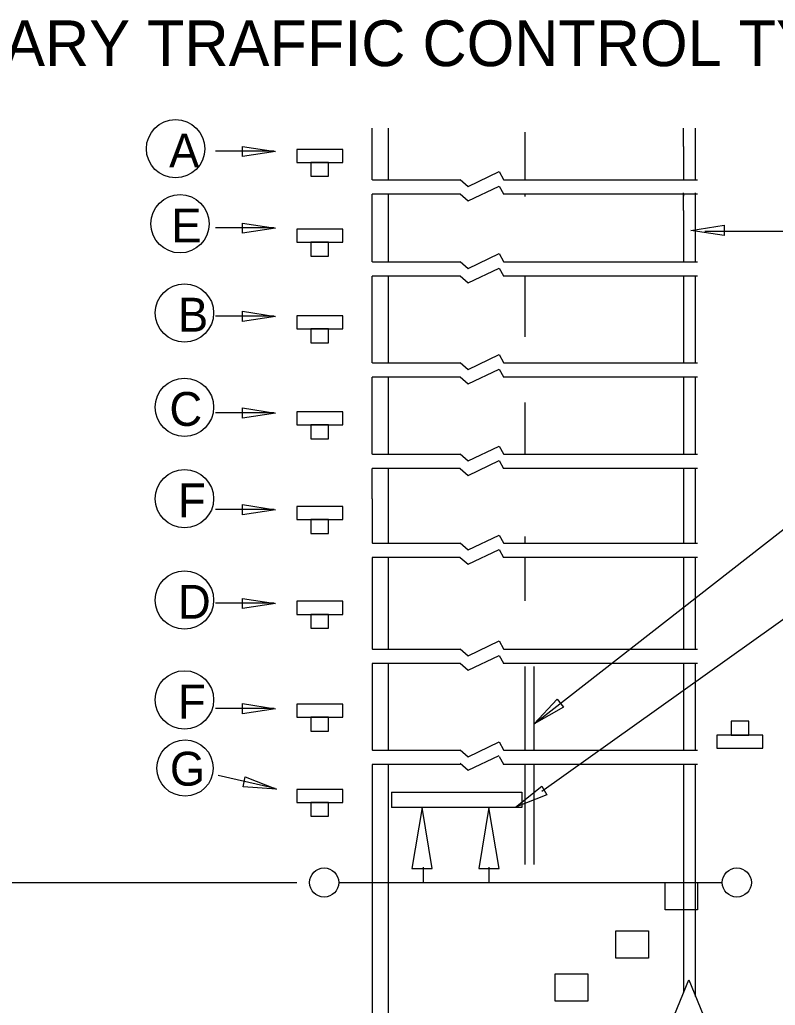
# Model space of a CAD drawing. Extents: x 1531.2 to 1538.6, y 1529.6 to 1539.7.
# Drawn here: x 1533.576 to 1535.359, y 1537.377 to 1539.704 of the extents above; entities that cross this region are included whole.
import ezdxf

# ---------------------------------------------------------------- set-up
doc = ezdxf.new("R2010")
doc.units = 0
for name, color, linetype in [('DETL-DIMS', 7, 'Continuous'), ('DETL-LINE', 7, 'Continuous'), ('DETL-NOTE', 7, 'Continuous'), ('DETL-TITL', 7, 'Continuous')]:
    doc.layers.add(name, color=color, linetype=linetype)

msp = doc.modelspace()

# ---------------------------------------------------------------- linework, layer by layer
at = {"layer": 'DETL-DIMS'}
for p, q in [((1534.1757, 1539.3929), (1534.0377, 1539.3929)), ((1534.6337, 1539.31), (1534.7074, 1539.3451)), ((1534.7074, 1539.3451), (1534.7174, 1539.3263)), ((1534.4085, 1539.3259), (1534.6147, 1539.3259)), ((1534.6147, 1539.3263), (1534.6337, 1539.31)), ((1534.7173, 1539.3259), (1535.1751, 1539.3259)), ((1534.6337, 1539.276), (1534.7074, 1539.311)), ((1534.7074, 1539.311), (1534.7174, 1539.2923)), ((1534.6149, 1539.2919), (1534.4085, 1539.2919)), ((1534.6147, 1539.2923), (1534.6337, 1539.276)), ((1535.1751, 1539.2919), (1534.7167, 1539.2919)), ((1534.1757, 1539.212), (1534.0377, 1539.212)), ((1535.1925, 1539.2044), (1535.7088, 1539.2044)), ((1534.4085, 1539.1323), (1534.6147, 1539.1323)), ((1534.6147, 1539.1327), (1534.6337, 1539.1164)), ((1534.6337, 1539.1164), (1534.7074, 1539.1515)), ((1534.7074, 1539.1515), (1534.7174, 1539.1327)), ((1534.7173, 1539.1323), (1535.1751, 1539.1323)), ((1534.6337, 1539.0824), (1534.7074, 1539.1174)), ((1534.7074, 1539.1174), (1534.7174, 1539.0987)), ((1534.6149, 1539.0983), (1534.4085, 1539.0983)), ((1534.6147, 1539.0987), (1534.6337, 1539.0824)), ((1535.1751, 1539.0983), (1534.7167, 1539.0983)), ((1534.1757, 1539.0038), (1534.0377, 1539.0038)), ((1534.6337, 1538.878), (1534.7074, 1538.9131)), ((1534.7074, 1538.9131), (1534.7174, 1538.8944)), ((1534.4085, 1538.8939), (1534.6147, 1538.8939)), ((1534.6147, 1538.8944), (1534.6337, 1538.878)), ((1534.6337, 1538.844), (1534.7074, 1538.879)), ((1534.7074, 1538.879), (1534.7174, 1538.8603)), ((1534.7173, 1538.8939), (1535.1751, 1538.8939)), ((1534.6149, 1538.8599), (1534.4085, 1538.8599)), ((1534.6147, 1538.8603), (1534.6337, 1538.844)), ((1535.1751, 1538.8599), (1534.7167, 1538.8599)), ((1534.1757, 1538.7755), (1534.0377, 1538.7755)), ((1534.7897, 1538.0412), (1535.7183, 1538.7668)), ((1534.6337, 1538.662), (1534.7074, 1538.6971)), ((1534.7074, 1538.6971), (1534.7174, 1538.6784)), ((1534.4085, 1538.6779), (1534.6147, 1538.6779)), ((1534.6147, 1538.6784), (1534.6337, 1538.662)), ((1534.7173, 1538.6779), (1535.1751, 1538.6779)), ((1534.6149, 1538.6439), (1534.4085, 1538.6439)), ((1534.6147, 1538.6443), (1534.6337, 1538.628)), ((1534.6337, 1538.628), (1534.7074, 1538.663)), ((1534.7074, 1538.663), (1534.7174, 1538.6443)), ((1535.1751, 1538.6439), (1534.7167, 1538.6439)), ((1534.1757, 1538.5473), (1534.0377, 1538.5473)), ((1534.8078, 1537.8823), (1535.7074, 1538.5239)), ((1534.6337, 1538.4521), (1534.7074, 1538.4871)), ((1534.7074, 1538.4871), (1534.7174, 1538.4684)), ((1534.4085, 1538.4679), (1534.6147, 1538.4679)), ((1534.6147, 1538.4684), (1534.6337, 1538.4521)), ((1534.7173, 1538.4679), (1535.1751, 1538.4679)), ((1534.6149, 1538.4339), (1534.4085, 1538.4339)), ((1534.6147, 1538.4344), (1534.6337, 1538.4181)), ((1534.6337, 1538.4181), (1534.7074, 1538.4531)), ((1534.7074, 1538.4531), (1534.7174, 1538.4344)), ((1535.1751, 1538.4339), (1534.7167, 1538.4339)), ((1534.1757, 1538.3259), (1534.0377, 1538.3259)), ((1534.6337, 1538.2021), (1534.7074, 1538.2371)), ((1534.7074, 1538.2371), (1534.7174, 1538.2184)), ((1534.4085, 1538.2179), (1534.6147, 1538.2179)), ((1534.6147, 1538.2184), (1534.6337, 1538.2021)), ((1534.6337, 1538.168), (1534.7074, 1538.203)), ((1534.7074, 1538.203), (1534.7174, 1538.1843)), ((1534.7173, 1538.2179), (1535.1751, 1538.2179)), ((1534.6149, 1538.1839), (1534.4085, 1538.1839)), ((1534.6147, 1538.1843), (1534.6337, 1538.168)), ((1535.1751, 1538.1839), (1534.7167, 1538.1839)), ((1534.1757, 1538.0777), (1534.0377, 1538.0777)), ((1534.6337, 1537.9637), (1534.7074, 1537.9987)), ((1534.7074, 1537.9987), (1534.7174, 1537.98)), ((1534.4085, 1537.9795), (1534.6147, 1537.9795)), ((1534.6147, 1537.98), (1534.6337, 1537.9637)), ((1534.6337, 1537.932), (1534.7074, 1537.967)), ((1534.7173, 1537.9795), (1535.1751, 1537.9795)), ((1534.6149, 1537.9455), (1534.4072, 1537.9455)), ((1534.6147, 1537.9483), (1534.6337, 1537.932)), ((1534.7074, 1537.9646), (1534.7174, 1537.9459)), ((1535.1751, 1537.9455), (1534.7167, 1537.9455)), ((1534.1783, 1537.8885), (1534.0436, 1537.9191)), ((1533.4083, 1537.6671), (1534.2295, 1537.6671))]:
    msp.add_line(p, q, dxfattribs=at)
for points in [[(1534.1795, 1539.3924), (1534.101, 1539.3804), (1534.101, 1539.4044)], [(1534.1795, 1539.2115), (1534.101, 1539.1995), (1534.101, 1539.2235)], [(1535.1597, 1539.2063), (1535.2383, 1539.2183), (1535.2383, 1539.1943)], [(1534.1795, 1539.0033), (1534.101, 1538.9913), (1534.101, 1539.0153)], [(1534.1795, 1538.7751), (1534.101, 1538.7631), (1534.101, 1538.7871)], [(1534.1795, 1538.5468), (1534.101, 1538.5348), (1534.101, 1538.5588)], [(1534.1795, 1538.3255), (1534.101, 1538.3135), (1534.101, 1538.3375)], [(1534.1795, 1538.0772), (1534.101, 1538.0652), (1534.101, 1538.0892)], [(1534.7897, 1538.0412), (1534.8438, 1538.0994), (1534.8587, 1538.0806)], [(1534.1818, 1537.8872), (1534.1026, 1537.8929), (1534.1079, 1537.9163)], [(1534.7455, 1537.8449), (1534.8077, 1537.8943), (1534.8197, 1537.8735)]]:
    msp.add_lwpolyline(points, close=True, dxfattribs=at)
at = {"layer": 'DETL-LINE'}
for p, q in [((1534.4072, 1539.3996), (1534.4072, 1539.4477)), ((1534.4456, 1539.4043), (1534.4456, 1539.4477)), ((1534.7687, 1539.3259), (1534.7687, 1539.4383)), ((1535.1419, 1539.4043), (1535.1419, 1539.4477)), ((1535.1706, 1539.3777), (1535.1706, 1539.4477)), ((1534.4072, 1539.3255), (1534.4072, 1539.3996)), ((1534.4456, 1539.3259), (1534.4456, 1539.4043)), ((1535.1419, 1539.4043), (1535.1419, 1539.3259)), ((1535.1706, 1539.3259), (1535.1706, 1539.3777)), ((1534.4085, 1539.3259), (1534.4072, 1539.3259)), ((1535.1419, 1539.2531), (1535.1419, 1539.2946)), ((1535.1706, 1539.2531), (1535.1706, 1539.2946)), ((1534.4085, 1539.2919), (1534.4072, 1539.2919)), ((1534.4072, 1539.2872), (1534.4072, 1539.2919)), ((1534.4072, 1539.2531), (1534.4072, 1539.2907)), ((1534.4456, 1539.2872), (1534.4456, 1539.2919)), ((1534.4456, 1539.2531), (1534.4456, 1539.2891)), ((1534.7687, 1539.2863), (1534.7687, 1539.2919)), ((1535.1419, 1539.2919), (1535.1419, 1539.2872)), ((1535.1706, 1539.2872), (1535.1706, 1539.2919)), ((1534.4072, 1539.1323), (1534.4072, 1539.2531)), ((1534.4456, 1539.1323), (1534.4456, 1539.2531)), ((1535.1419, 1539.2531), (1535.1419, 1539.1323)), ((1535.1706, 1539.1323), (1535.1706, 1539.2531)), ((1534.4085, 1539.1323), (1534.4072, 1539.1323)), ((1534.4085, 1539.0983), (1534.4072, 1539.0983)), ((1534.4072, 1538.8939), (1534.4072, 1539.0983)), ((1534.4456, 1538.8939), (1534.4456, 1539.0983)), ((1534.7687, 1538.9546), (1534.7687, 1539.0983)), ((1535.1419, 1539.0983), (1535.1419, 1538.8939)), ((1535.1706, 1538.8939), (1535.1706, 1539.0983)), ((1534.4085, 1538.8939), (1534.4072, 1538.8939)), ((1534.4085, 1538.8599), (1534.4072, 1538.8599)), ((1534.4072, 1538.6779), (1534.4072, 1538.8599)), ((1534.4456, 1538.6779), (1534.4456, 1538.8599)), ((1535.1419, 1538.8599), (1535.1419, 1538.6779)), ((1535.1706, 1538.6779), (1535.1706, 1538.8599)), ((1534.7687, 1538.6779), (1534.7687, 1538.7999)), ((1534.4085, 1538.6779), (1534.4072, 1538.6779)), ((1534.4072, 1538.5725), (1534.4072, 1538.6439)), ((1534.4085, 1538.6439), (1534.4072, 1538.6439)), ((1534.4456, 1538.4679), (1534.4456, 1538.6439)), ((1535.1419, 1538.6439), (1535.1419, 1538.4679)), ((1535.1706, 1538.5725), (1535.1706, 1538.6439)), ((1534.4072, 1538.5725), (1534.4072, 1538.4679)), ((1535.1706, 1538.4679), (1535.1706, 1538.5725)), ((1534.7687, 1538.4679), (1534.7687, 1538.4835)), ((1534.4085, 1538.4679), (1534.4072, 1538.4679)), ((1534.4085, 1538.4339), (1534.4072, 1538.4339)), ((1534.4072, 1538.4339), (1534.4072, 1538.2179)), ((1534.4456, 1538.2179), (1534.4456, 1538.4339)), ((1534.7687, 1538.3315), (1534.7687, 1538.4339)), ((1535.1419, 1538.4339), (1535.1419, 1538.2179)), ((1535.1706, 1538.2179), (1535.1706, 1538.4339)), ((1534.4085, 1538.2179), (1534.4072, 1538.2179)), ((1534.4085, 1538.1839), (1534.4072, 1538.1839)), ((1534.4072, 1538.1839), (1534.4072, 1537.9795)), ((1534.4456, 1537.9795), (1534.4456, 1538.1839)), ((1534.7687, 1537.9795), (1534.7687, 1538.1768)), ((1534.7897, 1537.9795), (1534.7897, 1538.1768)), ((1535.1419, 1538.1839), (1535.1419, 1537.9795)), ((1535.1706, 1537.9795), (1535.1706, 1538.1839)), ((1534.4085, 1537.9795), (1534.4072, 1537.9795)), ((1534.4085, 1537.9455), (1534.4072, 1537.9455)), ((1534.4072, 1537.9455), (1534.4072, 1533.711)), ((1534.4456, 1532.6352), (1534.4456, 1537.9455)), ((1534.7687, 1537.709), (1534.7687, 1537.9455)), ((1534.7897, 1537.709), (1534.7897, 1537.9455)), ((1535.1419, 1537.9455), (1535.1419, 1537.5333)), ((1535.1706, 1537.3975), (1535.1706, 1537.9455)), ((1534.4532, 1537.8799), (1534.7605, 1537.8799)), ((1534.4532, 1537.8799), (1534.4532, 1537.8439)), ((1534.7605, 1537.8799), (1534.7605, 1537.8439)), ((1534.7605, 1537.8439), (1534.4532, 1537.8439)), ((1534.5277, 1537.7031), (1534.5277, 1537.6668)), ((1534.6827, 1537.7031), (1534.6827, 1537.6668)), ((1534.3284, 1537.6668), (1535.2334, 1537.6668)), ((1535.1419, 1537.5333), (1535.1419, 1537.4065))]:
    msp.add_line(p, q, dxfattribs=at)
for points in [[(1534.3378, 1539.3667), (1534.3378, 1539.3975), (1534.2296, 1539.3975), (1534.2296, 1539.3667)], [(1534.3042, 1539.3667), (1534.2629, 1539.3667), (1534.2629, 1539.3339), (1534.3042, 1539.3339)], [(1534.3378, 1539.1782), (1534.3378, 1539.2091), (1534.2296, 1539.2091), (1534.2296, 1539.1782)], [(1534.3042, 1539.1782), (1534.2629, 1539.1782), (1534.2629, 1539.1454), (1534.3042, 1539.1454)], [(1534.3378, 1538.9738), (1534.3378, 1539.0047), (1534.2296, 1539.0047), (1534.2296, 1538.9738)], [(1534.3042, 1538.9738), (1534.2629, 1538.9738), (1534.2629, 1538.941), (1534.3042, 1538.941)], [(1534.3378, 1538.747), (1534.3378, 1538.7779), (1534.2296, 1538.7779), (1534.2296, 1538.747)], [(1534.3042, 1538.747), (1534.2629, 1538.747), (1534.2629, 1538.7142), (1534.3042, 1538.7142)], [(1534.3378, 1538.5234), (1534.3378, 1538.5543), (1534.2296, 1538.5543), (1534.2296, 1538.5234)], [(1534.3042, 1538.5234), (1534.2629, 1538.5234), (1534.2629, 1538.4907), (1534.3042, 1538.4907)], [(1534.3378, 1538.2998), (1534.3378, 1538.3307), (1534.2296, 1538.3307), (1534.2296, 1538.2998)], [(1534.3042, 1538.2998), (1534.2629, 1538.2998), (1534.2629, 1538.2671), (1534.3042, 1538.2671)], [(1534.3378, 1538.0571), (1534.3378, 1538.0879), (1534.2296, 1538.0879), (1534.2296, 1538.0571)], [(1534.3042, 1538.0571), (1534.2629, 1538.0571), (1534.2629, 1538.0243), (1534.3042, 1538.0243)], [(1535.2546, 1538.015), (1535.2959, 1538.015), (1535.2959, 1538.0478), (1535.2546, 1538.0478)], [(1535.221, 1538.015), (1535.221, 1537.9841), (1535.3292, 1537.9841), (1535.3292, 1538.015)], [(1534.3378, 1537.8558), (1534.3378, 1537.8867), (1534.2296, 1537.8867), (1534.2296, 1537.8558)], [(1534.3042, 1537.8558), (1534.2629, 1537.8558), (1534.2629, 1537.8231), (1534.3042, 1537.8231)], [(1534.5013, 1537.7), (1534.5493, 1537.7), (1534.5253, 1537.844)], [(1534.6587, 1537.7), (1534.7067, 1537.7), (1534.6827, 1537.844)], [(1535.0985, 1537.602), (1535.0985, 1537.6665), (1535.1753, 1537.6665), (1535.1753, 1537.602)], [(1534.9824, 1537.4882), (1534.9824, 1537.5527), (1535.0591, 1537.5527), (1535.0591, 1537.4882)], [(1534.8395, 1537.3864), (1534.8395, 1537.4509), (1534.9163, 1537.4509), (1534.9163, 1537.3864)], [(1535.2026, 1537.3196), (1535.1067, 1537.3196), (1535.1543, 1537.4371)]]:
    msp.add_lwpolyline(points, close=True, dxfattribs=at)
for centre in [(1534.2939, 1537.6668), (1535.2679, 1537.6668)]:
    msp.add_circle(centre, 0.0344, dxfattribs=at)
at = {"layer": 'DETL-NOTE'}
for centre, radius in [((1533.9433, 1539.399), 0.0688), ((1533.9539, 1539.2218), 0.0688), ((1533.9644, 1539.0113), 0.0688), ((1533.9644, 1538.7887), 0.0688), ((1533.9644, 1538.5729), 0.0688), ((1533.9644, 1538.3335), 0.0688), ((1533.9644, 1538.098), 0.0688), ((1533.9657, 1537.937), 0.0664)]:
    msp.add_circle(centre, radius, dxfattribs=at)

# ---------------------------------------------------------------- texts
for s, p in [('A', (1533.9281, 1539.3548)), ('E', (1533.9336, 1539.1777)), ('B', (1533.9491, 1538.9672)), ('C', (1533.9289, 1538.7447)), ('F', (1533.9491, 1538.5288)), ('D', (1533.9491, 1538.2895)), ('F', (1533.9491, 1538.0539)), ('G', (1533.93, 1537.8954))]:
    msp.add_text(s, height=0.08, dxfattribs=at).set_placement(p)
at = {"layer": 'DETL-TITL'}
msp.add_text('TEMPORARY TRAFFIC CONTROL TYPICAL APPLICATION', height=0.108, dxfattribs=at).set_placement((1532.9213, 1539.5939))

doc.saveas('drawing.dxf')
